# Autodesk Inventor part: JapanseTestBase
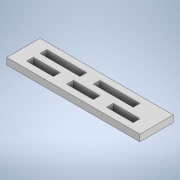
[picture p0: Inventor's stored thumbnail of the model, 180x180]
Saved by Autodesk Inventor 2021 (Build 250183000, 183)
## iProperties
Created: 2026-10
Part Number: JapanseTestBase
Material: Generic
Document SubType Name: Modeling
Designer: hp
Density: 1 g/cm^3
Appearance: Default
Author: hp
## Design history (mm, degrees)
sketch "Sketch1" dims "d27" = 10
  geometry: L1 (0, 0)-(100, 0); L2 (100, 0)-(100, -25); L3 (100, -25)-(0, -25); L4 (0, -25)-(0, 0); L5 (90, -15)-(60, -15); L6 (60, -15)-(60, -20); L7 (60, -20)-(90, -20); L8 (90, -20)-(90, -15); L9 (90, -5)-(70, -5); L10 (70, -5)-(70, -10); L11 (70, -10)-(90, -10); L12 (90, -10)-(90, -5); L13 (20, -15)-(20, -20); L14 (50, -15)-(20, -15); L15 (20, -20)-(50, -20); L16 (50, -20)-(50, -15); L17 (40, -5)-(40, -10); L18 (60, -5)-(40, -5); L19 (40, -10)-(60, -10); L20 (60, -10)-(60, -5); L21 (10, -5)-(10, -10); L22 (30, -5)-(10, -5); L23 (10, -10)-(30, -10); L24 (30, -10)-(30, -5)
  constraints: 48 end point, 8 parallel, 5 horizontal, 4 perpendicular, 2 collinear, 15 other
  dimensions: "d0" = 100 distance of L2.end L3.end; "d1" = 25 distance of L1.end L2.end; "d2" = 30 distance of L7.end L6.end; "d3" = 5 distance of L6.end L5.end; "d4" = 20 distance of L11.end L10.end; "d5" = 5 distance of L10.end L9.end; "d15" = 5 distance between parallel lines of L3 L7; "d16" = 10 distance between parallel lines of L2 L8; "d17" = 30 distance of L15.end L13.end; "d18" = 5 distance of L13.end L13.start; "d19" = 10 distance between parallel lines of L16 L6; "d20" = 5 distance between parallel lines of L1 L9; "d21" = 10 distance between parallel lines of L2 L12; "d24" = 30 distance of L10.end L17.end
extrude "Extrusion1" new body sketch "Sketch1" distance "d29" = 5; taper "d30" = 0 deg
body "Solid1"
